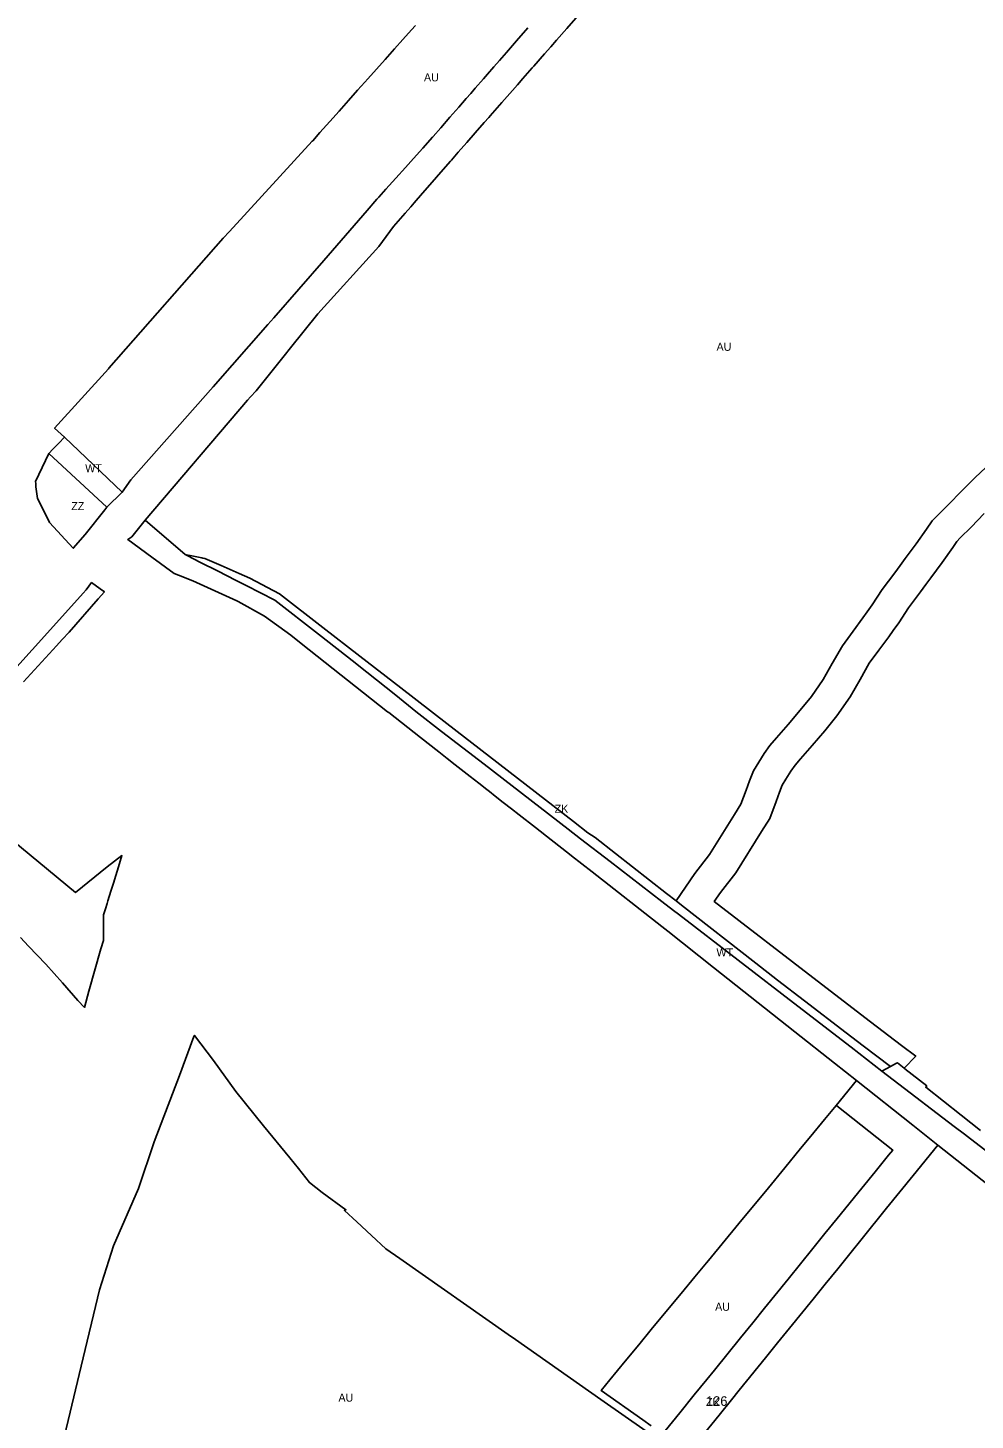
# Model space of a CAD drawing. Extents: x -537068 to -534056, y -1176840 to -1172401.
# Drawn here: x -535534 to -534942, y -1175088 to -1174218 of the extents above; entities that cross this region are included whole.
import ezdxf

# ---------------------------------------------------------------- set-up
doc = ezdxf.new("R2010")
doc.units = 0
for name, color, linetype in [('90640013', 7, 'Continuous'), ('90670013', 7, 'Continuous'), ('90670023', 7, 'Continuous'), ('90710013', 7, 'Continuous'), ('90710023', 7, 'Continuous'), ('90750013', 7, 'Continuous'), ('ID_navrh', 7, 'Continuous')]:
    doc.layers.add(name, color=color, linetype=linetype)

msp = doc.modelspace()

# ---------------------------------------------------------------- linework, layer by layer
at = {"layer": '90640013'}
msp.add_lwpolyline([(-535484.19, -1174517.6), (-535520.47, -1174483.88), (-535517.93, -1174481.25), (-535514.27, -1174477.46), (-535510.67, -1174473.73), (-535474.62, -1174508.21)], close=True, dxfattribs=at)
msp.add_lwpolyline([(-534880.64, -1174982.65), (-534964.8, -1174916.06), (-534980.49, -1174903.64), (-535015.64, -1174875.82), (-535029.37, -1174864.97), (-535054.2, -1174845.36), (-535105.18, -1174805.1), (-535133.64, -1174782.42), (-535137.34, -1174779.47), (-535180.95, -1174745.42), (-535193.83, -1174735.34), (-535195.16, -1174734.3), (-535206.62, -1174725.33), (-535216.41, -1174717.66), (-535226.54, -1174709.73), (-535231.33, -1174705.98), (-535236.44, -1174701.98), (-535241.43, -1174698.08), (-535245.09, -1174695.22), (-535246.75, -1174693.92), (-535251.68, -1174690.05), (-535257.11, -1174685.79), (-535266.49, -1174678.43), (-535271.47, -1174674.53), (-535276.83, -1174670.32), (-535288.12, -1174661.46), (-535307.95, -1174645.91), (-535308.72, -1174645.31), (-535362.87, -1174602.65), (-535369.33, -1174597.57), (-535385.62, -1174585.63), (-535402.21, -1174576.49), (-535403.06, -1174576.02), (-535430.46, -1174563.51), (-535439.36, -1174560.05), (-535442.11, -1174558.98), (-535456.08, -1174548.77), (-535471.15, -1174537.77), (-535468.67, -1174536.04), (-535460.36, -1174525.57), (-535435.3, -1174547.14), (-535433.71, -1174547.94), (-535426.06, -1174551.8), (-535414.58, -1174557.59), (-535403.74, -1174563.06), (-535397.15, -1174566.38), (-535379.29, -1174575.66), (-535352.01, -1174596.91), (-535329.12, -1174614.73), (-535327.76, -1174615.79), (-535303.71, -1174635.06), (-535291.1, -1174645.17), (-535274.97, -1174657.64), (-535248.41, -1174678.16), (-535195.85, -1174718.78), (-535188.26, -1174724.64), (-535169.68, -1174738.93), (-535137.34, -1174763.8), (-535130.04, -1174769.42), (-535126.85, -1174771.88), (-535052.41, -1174829.3), (-535019.11, -1174854.99), (-534999.77, -1174869.82), (-534992.69, -1174875.28), (-534954.69, -1174904.38), (-534948.24, -1174909.32), (-534944.54, -1174912.26), (-534853.75, -1174981.84)], dxfattribs=at)
at = {"layer": '90670013'}
msp.add_lwpolyline([(-535484.19, -1174517.6), (-535485.44, -1174519.17), (-535497.79, -1174534.64), (-535505.18, -1174543.16), (-535520.16, -1174527.13), (-535523.26, -1174520.67), (-535527.55, -1174512.19), (-535528.62, -1174504.76), (-535528.7, -1174502.71), (-535528.74, -1174501.56), (-535520.47, -1174483.88)], close=True, dxfattribs=at)
at = {"layer": '90670023'}
for points in [[(-535542.3, -1174619.4), (-535519.4, -1174593.91), (-535499.11, -1174571.32), (-535497.25, -1174569.07), (-535493.78, -1174564.65), (-535488.44, -1174568.5), (-535485.78, -1174570.42), (-535489.61, -1174574.77), (-535507.87, -1174595.51), (-535512.09, -1174600.14), (-535515.65, -1174604.06), (-535536.25, -1174626.67)], [(-535566.78, -1174706.43), (-535503.82, -1174758.26), (-535484.01, -1174742.28), (-535474.82, -1174735.18), (-535476.38, -1174740.24), (-535480.16, -1174752.5), (-535481.66, -1174757.38), (-535483.52, -1174763.4), (-535484.03, -1174765.07), (-535485.11, -1174768.58), (-535486.26, -1174772.31), (-535486.35, -1174788.34), (-535487.92, -1174793.5), (-535495.38, -1174819.84), (-535498.26, -1174830.11), (-535502.32, -1174825.67), (-535511.87, -1174814.73), (-535522.3, -1174803.11), (-535533.16, -1174791.87), (-535538.23, -1174786.31)]]:
    msp.add_lwpolyline(points, dxfattribs=at)
at = {"layer": '90710013'}
msp.add_lwpolyline([(-534994.52, -1174867.04), (-534999.77, -1174869.82), (-535019.11, -1174854.99), (-535052.41, -1174829.3), (-535126.85, -1174771.88), (-535130.04, -1174769.42), (-535137.34, -1174763.8), (-535169.68, -1174738.93), (-535188.26, -1174724.64), (-535195.85, -1174718.78), (-535248.41, -1174678.16), (-535274.97, -1174657.64), (-535291.1, -1174645.17), (-535303.71, -1174635.06), (-535327.76, -1174615.79), (-535329.12, -1174614.73), (-535352.01, -1174596.91), (-535379.29, -1174575.66), (-535397.15, -1174566.38), (-535403.74, -1174563.06), (-535414.58, -1174557.59), (-535426.06, -1174551.8), (-535433.71, -1174547.94), (-535435.3, -1174547.14), (-535433.52, -1174547.48), (-535432.16, -1174547.74), (-535424.83, -1174549.15), (-535424.16, -1174549.28), (-535422.89, -1174549.52), (-535412.8, -1174553.99), (-535401.53, -1174558.99), (-535394.85, -1174561.95), (-535376.22, -1174571.71), (-535349.24, -1174592.6), (-535326.08, -1174610.53), (-535300.51, -1174630.33), (-535271.76, -1174652.58), (-535245.08, -1174673.24), (-535192.6, -1174713.87), (-535183.52, -1174720.9), (-535179.1, -1174723.82), (-535166.23, -1174733.88), (-535134.36, -1174758.81), (-535128.51, -1174763.38), (-535125, -1174766.13), (-535078.62, -1174802.4), (-535065.07, -1174812.99), (-535048.27, -1174825.86), (-535022.08, -1174845.92), (-535011.48, -1174854.04)], close=True, dxfattribs=at)
at = {"layer": '90710023'}
for points in [[(-534935.81, -1174521.55), (-534944.09, -1174529.91), (-534950.81, -1174536.69), (-534953.07, -1174538.97), (-534955.59, -1174542.61), (-534962.24, -1174552.18), (-534969.25, -1174561.6), (-534972.46, -1174565.91), (-534975.79, -1174570.4), (-534983.22, -1174580.37), (-534989.32, -1174589.88), (-534992.8, -1174594.66), (-534995.59, -1174598.48), (-535001.72, -1174606.86), (-535007.71, -1174615.05), (-535013.51, -1174625.18), (-535019.66, -1174635.92), (-535027.92, -1174647.9), (-535035.53, -1174657.23), (-535043.35, -1174666.33), (-535050.63, -1174674.77), (-535053.99, -1174678.69), (-535056.71, -1174682.56), (-535059.84, -1174687.5), (-535062.16, -1174691.15), (-535063.81, -1174695.57), (-535065.97, -1174701.34), (-535069.96, -1174712.04), (-535075.09, -1174720.12), (-535091.14, -1174746.08), (-535100.72, -1174758.18), (-535104.57, -1174763.81), (-535040.19, -1174813.46), (-535006.92, -1174839.14), (-534987.6, -1174853.95), (-534978.7, -1174860.52), (-534985.93, -1174868.07), (-534990.18, -1174864.74), (-534990.63, -1174864.98), (-534994.52, -1174867.04), (-535011.48, -1174854.04), (-535022.08, -1174845.92), (-535048.27, -1174825.86), (-535065.07, -1174812.99), (-535078.62, -1174802.4), (-535125, -1174766.13), (-535128.51, -1174763.38), (-535116.83, -1174746.32), (-535107.54, -1174734.58), (-535092.04, -1174709.51), (-535087.97, -1174703.09), (-535084.7, -1174694.34), (-535082.54, -1174688.56), (-535080.16, -1174682.2), (-535076.73, -1174676.79), (-535073.35, -1174671.46), (-535069.8, -1174666.4), (-535065.79, -1174661.73), (-535058.51, -1174653.28), (-535050.86, -1174644.39), (-535043.93, -1174635.89), (-535036.6, -1174625.25), (-535030.86, -1174615.24), (-535024.51, -1174604.15), (-535017.87, -1174595.06), (-535011.74, -1174586.68), (-535008.96, -1174582.87), (-535005.83, -1174578.58), (-534999.68, -1174568.99), (-534991.84, -1174558.46), (-534988.51, -1174553.98), (-534985.3, -1174549.66), (-534978.48, -1174540.5), (-534972.02, -1174531.2), (-534968.5, -1174526.13), (-534965.02, -1174522.62), (-534958.3, -1174515.83), (-534950.01, -1174507.47), (-534941.55, -1174498.93), (-534934.92, -1174492.67)], [(-535135.27, -1175094.64), (-535126.17, -1175083.41), (-535117.11, -1175072.23), (-535109.34, -1175062.64), (-535104.52, -1175056.7), (-535088.14, -1175036.49), (-535080.57, -1175027.15), (-535073.11, -1175017.94), (-535058.41, -1174999.8), (-535050.74, -1174990.33), (-535042.96, -1174980.73), (-535035.42, -1174971.43), (-535027.73, -1174961.94), (-535012.39, -1174943), (-535004.11, -1174932.79), (-534995.76, -1174922.48), (-534993.08, -1174919.18), (-535028.05, -1174891.5), (-535028.38, -1174891.27), (-535015.64, -1174875.82), (-534980.49, -1174903.64), (-534964.8, -1174916.06), (-534964.95, -1174916.23), (-534980.22, -1174935.07), (-534988.57, -1174945.38), (-534996.85, -1174955.59), (-535012.19, -1174974.53), (-535019.88, -1174984.02), (-535027.42, -1174993.32), (-535035.2, -1175002.92), (-535042.87, -1175012.39), (-535057.57, -1175030.53), (-535065.03, -1175039.74), (-535072.6, -1175049.08), (-535088.99, -1175069.3), (-535093.81, -1175075.24), (-535101.57, -1175084.82), (-535110.63, -1175096)]]:
    msp.add_lwpolyline(points, dxfattribs=at)
at = {"layer": '90750013'}
for points in [[(-534934.92, -1174492.67), (-534941.55, -1174498.93), (-534950.01, -1174507.47), (-534958.3, -1174515.83), (-534965.02, -1174522.62), (-534968.5, -1174526.13), (-534972.02, -1174531.2), (-534978.48, -1174540.5), (-534985.3, -1174549.66), (-534988.51, -1174553.98), (-534991.84, -1174558.46), (-534999.68, -1174568.99), (-535005.83, -1174578.58), (-535008.96, -1174582.87), (-535011.74, -1174586.68), (-535017.87, -1174595.06), (-535024.51, -1174604.15), (-535030.86, -1174615.24), (-535036.6, -1174625.25), (-535043.93, -1174635.89), (-535050.86, -1174644.39), (-535058.51, -1174653.28), (-535065.79, -1174661.73), (-535069.8, -1174666.4), (-535073.35, -1174671.46), (-535076.73, -1174676.79), (-535080.16, -1174682.2), (-535082.54, -1174688.56), (-535084.7, -1174694.34), (-535087.97, -1174703.09), (-535092.04, -1174709.51), (-535107.54, -1174734.58), (-535116.83, -1174746.32), (-535128.51, -1174763.38), (-535134.36, -1174758.81), (-535166.23, -1174733.88), (-535179.1, -1174723.82), (-535183.52, -1174720.9), (-535192.6, -1174713.87), (-535245.08, -1174673.24), (-535271.76, -1174652.58), (-535300.51, -1174630.33), (-535326.08, -1174610.53), (-535349.24, -1174592.6), (-535376.22, -1174571.71), (-535394.85, -1174561.95), (-535401.53, -1174558.99), (-535412.8, -1174553.99), (-535422.89, -1174549.52), (-535424.16, -1174549.28), (-535424.83, -1174549.15), (-535432.16, -1174547.74), (-535433.52, -1174547.48), (-535435.3, -1174547.14), (-535460.36, -1174525.57), (-535396.32, -1174450.64), (-535394.37, -1174448.56), (-535390.89, -1174444.84), (-535373.49, -1174423.05), (-535369.36, -1174417.88), (-535352.34, -1174396.71), (-535314.14, -1174354.58), (-535305.02, -1174342.09), (-535297.83, -1174333.87), (-535294.26, -1174329.79), (-535292.22, -1174327.44), (-535286.89, -1174321.3), (-535280.86, -1174314.35), (-535275.5, -1174308.18), (-535269.54, -1174301.33), (-535268.91, -1174300.6), (-535264.65, -1174295.74), (-535259.33, -1174289.67), (-535254.06, -1174283.66), (-535248.44, -1174277.26), (-535245.53, -1174273.95), (-535243.51, -1174271.64), (-535243.22, -1174271.31), (-535237.35, -1174264.63), (-535230.74, -1174257.1), (-535227.61, -1174253.54), (-535224.16, -1174249.62), (-535218.42, -1174243.09), (-535217.4, -1174241.92), (-535210.61, -1174234.16), (-535206.81, -1174229.82), (-535203.2, -1174225.7), (-535196.74, -1174218.33), (-535189.68, -1174210.28)], [(-535221.11, -1174217.93), (-535228.18, -1174226.08), (-535234.55, -1174233.42), (-535238.87, -1174238.39), (-535242.31, -1174242.35), (-535246.39, -1174247.05), (-535248.9, -1174249.93), (-535253.95, -1174255.73), (-535256.81, -1174259.01), (-535259.64, -1174262.26), (-535264.3, -1174267.6), (-535269.77, -1174273.88), (-535275.54, -1174280.5), (-535280.23, -1174285.88), (-535280.67, -1174286.37), (-535286.71, -1174293.1), (-535292.62, -1174299.68), (-535297.67, -1174305.31), (-535303.68, -1174312.01), (-535309.79, -1174318.83), (-535314.2, -1174323.75), (-535315.43, -1174325.17), (-535321.49, -1174332.16), (-535348.53, -1174363.33), (-535379.86, -1174399.13), (-535383.65, -1174403.46), (-535417.86, -1174442.33), (-535469.32, -1174500.48), (-535474.62, -1174508.21), (-535510.67, -1174473.73), (-535516.92, -1174468.22), (-535483.27, -1174431.05), (-535482.99, -1174430.74), (-535411.51, -1174349.5), (-535407.64, -1174345.3), (-535355.87, -1174288.85), (-535355.58, -1174288.54), (-535351.08, -1174283.49), (-535344.87, -1174276.52), (-535339.12, -1174270.06), (-535333.17, -1174263.38), (-535327.51, -1174257.03), (-535323, -1174251.96), (-535321.14, -1174249.88), (-535315.67, -1174243.75), (-535310.29, -1174237.73), (-535304.39, -1174231.13), (-535299.26, -1174225.39), (-535293.88, -1174219.37), (-535291.39, -1174216.58)], [(-534938.24, -1174906.9), (-534950.35, -1174897.34), (-534972.43, -1174879.91), (-534971.8, -1174879.12), (-534985.56, -1174868.36), (-534985.93, -1174868.07), (-534978.7, -1174860.52), (-534987.6, -1174853.95), (-535006.92, -1174839.14), (-535040.19, -1174813.46), (-535104.57, -1174763.81), (-535100.72, -1174758.18), (-535091.14, -1174746.08), (-535075.09, -1174720.12), (-535069.96, -1174712.04), (-535065.97, -1174701.34), (-535063.81, -1174695.57), (-535062.16, -1174691.15), (-535059.84, -1174687.5), (-535056.71, -1174682.56), (-535053.99, -1174678.69), (-535050.63, -1174674.77), (-535043.35, -1174666.33), (-535035.53, -1174657.23), (-535027.92, -1174647.9), (-535019.66, -1174635.92), (-535013.51, -1174625.18), (-535007.71, -1174615.05), (-535001.72, -1174606.86), (-534995.59, -1174598.48), (-534992.8, -1174594.66), (-534989.32, -1174589.88), (-534983.22, -1174580.37), (-534975.79, -1174570.4), (-534972.46, -1174565.91), (-534969.25, -1174561.6), (-534962.24, -1174552.18), (-534955.59, -1174542.61), (-534953.07, -1174538.97), (-534950.81, -1174536.69), (-534944.09, -1174529.91), (-534935.81, -1174521.55)], [(-535516.52, -1175122.16), (-535500.18, -1175054.15), (-535488.9, -1175006.63), (-535479.97, -1174978.96), (-535464.48, -1174943.31), (-535454.72, -1174913.99), (-535438.91, -1174872.67), (-535429.82, -1174848.24), (-535429.42, -1174847.62), (-535417.66, -1174863.32), (-535403.69, -1174882.59), (-535386.22, -1174904.06), (-535369.87, -1174924.08), (-535364.5, -1174930.66), (-535357.59, -1174939.56), (-535349.55, -1174945.71), (-535334.8, -1174956.49), (-535335.79, -1174956.95), (-535327.96, -1174964.15), (-535318.81, -1174972.57), (-535309.83, -1174980.83), (-535301.06, -1174986.97), (-535233.44, -1175034.37), (-535228.85, -1175037.59), (-535175.51, -1175074.96), (-535147.24, -1175094.77)], [(-535144.09, -1175091.41), (-535149.3, -1175087.74), (-535175.34, -1175069.39), (-535169.92, -1175062.83), (-535160.18, -1175051.04), (-535151.84, -1175040.95), (-535143.93, -1175031.38), (-535134.77, -1175020.29), (-535125.23, -1175008.74), (-535116.71, -1174998.43), (-535109.44, -1174989.63), (-535108.22, -1174988.14), (-535089.3, -1174965.19), (-535070.78, -1174942.72), (-535060.48, -1174930.22), (-535050.64, -1174918.28), (-535044.3, -1174910.58), (-535035.75, -1174900.21), (-535028.38, -1174891.27), (-535028.05, -1174891.5), (-534993.08, -1174919.18), (-534995.76, -1174922.48), (-535004.11, -1174932.79), (-535012.39, -1174943), (-535027.73, -1174961.94), (-535035.42, -1174971.43), (-535042.96, -1174980.73), (-535050.74, -1174990.33), (-535058.41, -1174999.8), (-535073.11, -1175017.94), (-535080.57, -1175027.15), (-535088.14, -1175036.49), (-535104.52, -1175056.7), (-535109.34, -1175062.64), (-535117.11, -1175072.23), (-535126.17, -1175083.41), (-535135.27, -1175094.64)], [(-535110.63, -1175096), (-535101.57, -1175084.82), (-535093.81, -1175075.24), (-535088.99, -1175069.3), (-535072.6, -1175049.08), (-535065.03, -1175039.74), (-535057.57, -1175030.53), (-535042.87, -1175012.39), (-535035.2, -1175002.92), (-535027.42, -1174993.32), (-535019.88, -1174984.02), (-535012.19, -1174974.53), (-534996.85, -1174955.59), (-534988.57, -1174945.38), (-534980.22, -1174935.07), (-534964.95, -1174916.23), (-534964.8, -1174916.06), (-534880.64, -1174982.65)]]:
    msp.add_lwpolyline(points, dxfattribs=at)

# ---------------------------------------------------------------- texts
at = {"layer": '90640013'}
for rotation, p in [(0, (-535497.76, -1174495.66)), (360, (-535103.22, -1174798.25))]:
    msp.add_text('WT', height=5, rotation=rotation, dxfattribs=at).set_placement(p)
at = {"layer": '90670013'}
msp.add_text('ZZ', height=5, rotation=360, dxfattribs=at).set_placement((-535506.46, -1174519.34))
at = {"layer": '90710013'}
msp.add_text('ZK', height=5, rotation=360, dxfattribs=at).set_placement((-535204.37, -1174708.48))
at = {"layer": '90710023'}
msp.add_text('ZK', height=5, rotation=360, dxfattribs=at).set_placement((-535109.75, -1175079.03))
at = {"layer": '90750013'}
for rotation, p in [(0, (-535286.04, -1174251.47)), (0, (-535103.18, -1174419.83)), (0, (-535104.07, -1175019.62)), (360, (-535339.49, -1175076.4))]:
    msp.add_text('AU', height=5, rotation=rotation, dxfattribs=at).set_placement(p)
at = {"layer": 'ID_navrh'}
msp.add_text('126', height=6, rotation=360, dxfattribs=at).set_placement((-535109.75, -1175079.03))

doc.saveas('drawing.dxf')
